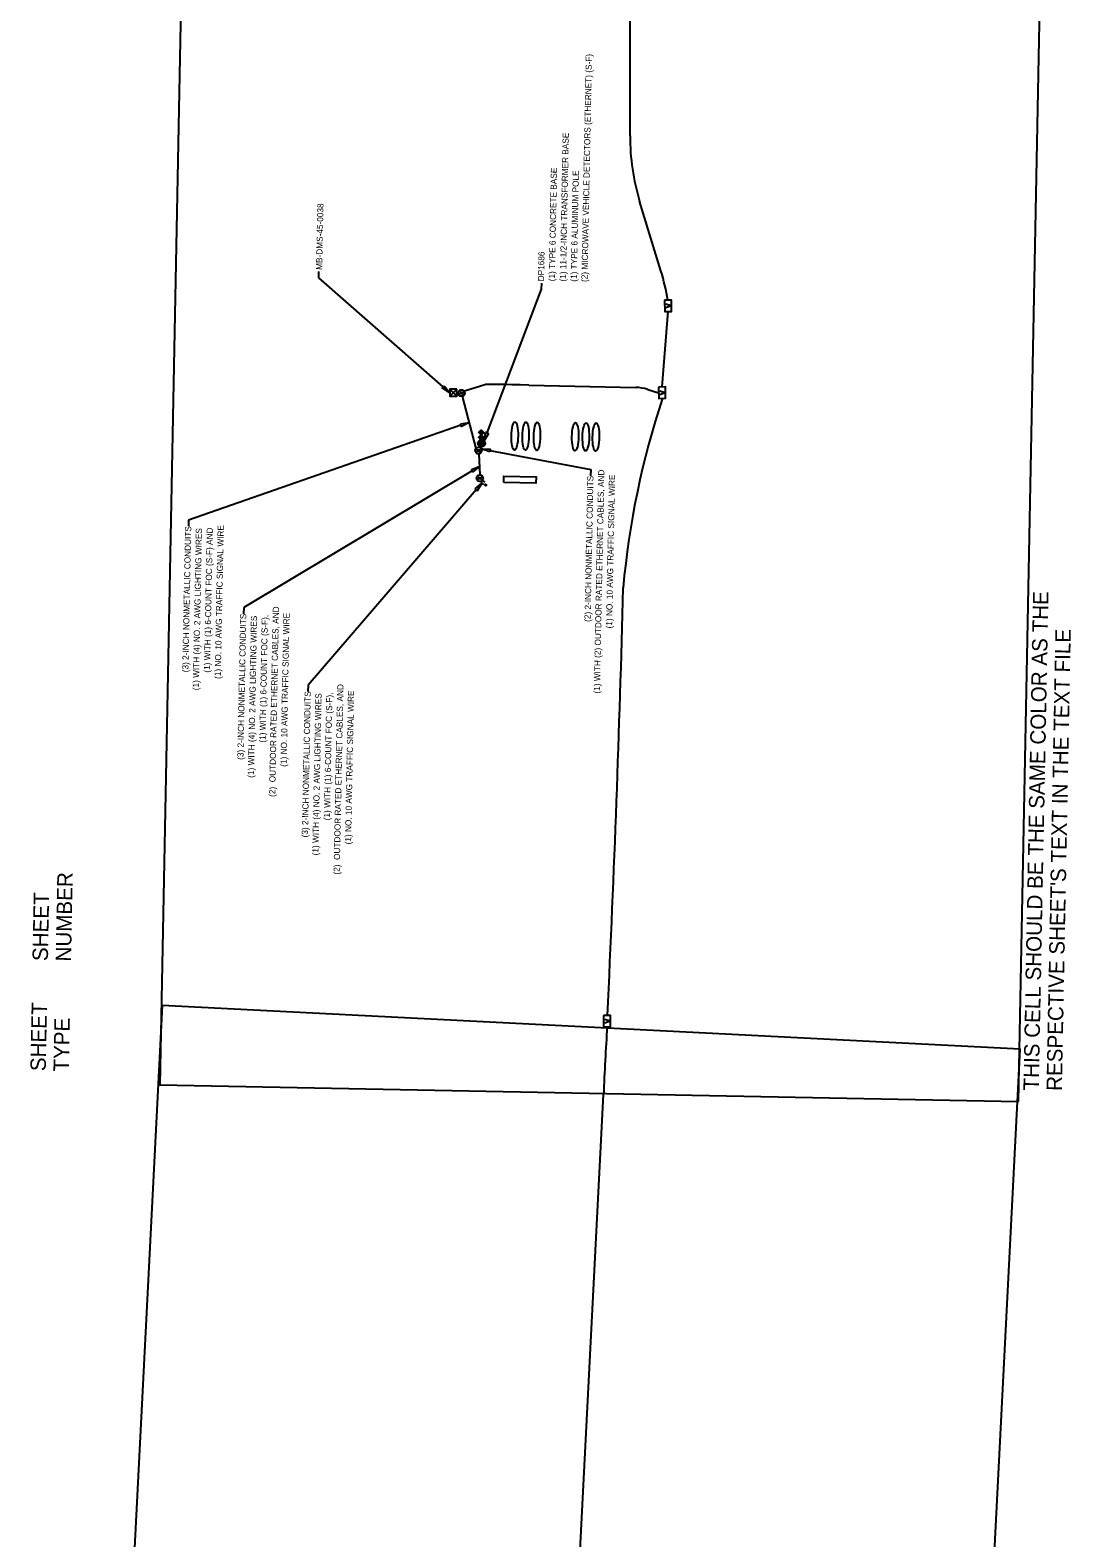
# Model space of a CAD drawing. Extents: x 601462 to 605493, y 331960 to 402715.
# Drawn here: x 602451 to 603632, y 391608 to 393320 of the extents above; entities that cross this region are included whole.
import ezdxf

# ---------------------------------------------------------------- set-up
doc = ezdxf.new("R2010")
doc.units = 0
for name, color, linetype in [('Default', 7, 'Continuous'), ('P_FTMS', 7, 'Continuous'), ('P_FTMSConduit', 7, 'Continuous'), ('P_MISC_TXT_1A (Construction)', 7, 'Continuous'), ('P_MISC_TXT_1B (Construction)', 7, 'Continuous')]:
    doc.layers.add(name, color=color, linetype=linetype)

# ---------------------------------------------------------------- blocks, each defined once
blk = doc.blocks.new('FMD')
at = {"layer": 'P_FTMS'}
for p, q in [((17, 18), (-17, 18)), ((-16, 16), (-16, 18)), ((16, 16), (-16, 16)), ((-15, 15), (-15, 20)), ((15, 19), (-15, 19)), ((15, 15), (-15, 15)), ((14, 20), (-14, 20)), ((13, 22), (-13, 22)), ((-13, 13), (-13, 21)), ((13, 13), (-13, 13)), ((-12, 12), (-12, 23)), ((12, 12), (-12, 12)), ((11, 23), (-11, 23)), ((10, 25), (-10, 25)), ((-10, 10), (-10, 24)), ((10, 10), (-10, 10)), ((-9, 9), (-9, 26)), ((9, 9), (-9, 9)), ((8, 26), (-8, 26)), ((7, 28), (-7, 28)), ((-7, 7), (-7, 27)), ((7, 7), (-7, 7)), ((-6, 6), (-6, 29)), ((6, 6), (-6, 6)), ((5, 29), (-5, 29)), ((4, 31), (-4, 31)), ((-4, 4), (-4, 30)), ((4, 4), (-4, 4)), ((-3, 3), (-3, 32)), ((3, 3), (-3, 3)), ((2, 32), (-2, 32)), ((1, 34), (-1, 34)), ((-1, 1), (-1, 33)), ((1, 1), (-1, 1)), ((0, 0), (0, 34)), ((1, 1), (1, 33)), ((3, 3), (3, 32)), ((4, 4), (4, 30)), ((6, 6), (6, 29)), ((7, 7), (7, 27)), ((9, 9), (9, 26)), ((10, 10), (10, 24)), ((12, 12), (12, 23)), ((13, 13), (13, 21)), ((15, 15), (15, 20)), ((16, 16), (16, 18))]:
    blk.add_line(p, q, dxfattribs=at)
blk.add_lwpolyline([(-17, 17), (0, 34), (17, 17), (0, 0)], close=True, dxfattribs=at)
blk = doc.blocks.new('FMB')
at = {"layer": 'P_FTMS'}
for p, q in [((24, -24), (-24, 24)), ((-24, -24), (24, 24))]:
    blk.add_line(p, q, dxfattribs=at)
blk.add_lwpolyline([(24, -24), (24, 24), (-24, 24), (-24, -24)], close=True, dxfattribs=at)
blk = doc.blocks.new('POINT_DISPLAY')
at = {"layer": 'Default'}
blk.add_line((0, 0), (0, 0), dxfattribs=at)
blk = doc.blocks.new('_U229')
at = {"layer": 'P_FTMS'}
for p, q in [((-4.5, 3.2), (1.5, -0.2)), ((-4.4, 2.8), (1.3, -0.4)), ((-4.3, 3.5), (1.8, 0)), ((-3.9, 3.4), (-4.3, 2.6)), ((-4.3, 2.4), (1, -0.6)), ((-3.5, 3.4), (-4.2, 2.2)), ((-4.2, 2), (0.7, -0.8)), ((-3.2, 3.3), (-4.1, 1.7)), ((-4.1, 1.6), (0.5, -1)), ((-2.9, 3.3), (-4, 1.3)), ((-4, 1.2), (0.2, -1.2)), ((-2.6, 3.2), (-3.9, 0.9)), ((-2.2, 3.2), (-3.8, 0.5)), ((-3.8, 0.7), (0, -1.4)), ((-1.9, 3.2), (-3.7, 0.1)), ((-3.7, 0.3), (-0.3, -1.6)), ((-3.5, 3.4), (2, 0.2)), ((-1.6, 3.1), (-3.5, -0.3)), ((-1.3, 3.1), (-3.4, -0.7)), ((-0.9, 3), (-3.3, -1.2)), ((-0.6, 3), (-3.2, -1.6)), ((-0.3, 2.9), (-3.1, -2)), ((0, 2.9), (-3, -2.4)), ((0.4, 2.8), (-2.9, -2.8)), ((-2.7, 3.3), (2.3, 0.4)), ((0.7, 2.8), (-2.7, -3.2)), ((1, 2.8), (-2.5, -3.4)), ((-1.9, 3.2), (2.5, 0.6)), ((1.3, 2.7), (-1.8, -2.9)), ((1.7, 2.7), (-1.2, -2.3)), ((-1.1, 3), (2.8, 0.8)), ((2, 2.6), (-0.5, -1.8)), ((-0.3, 2.9), (3.1, 1)), ((2.3, 2.6), (0.1, -1.3)), ((0.5, 2.8), (3.3, 1.2)), ((2.6, 2.5), (0.7, -0.8)), ((1.3, 2.7), (3.6, 1.4)), ((3, 2.5), (1.4, -0.3)), ((3.3, 2.4), (2, 0.2)), ((2.2, 2.6), (3.8, 1.6)), ((3.6, 2.4), (2.7, 0.7)), ((3, 2.5), (4.1, 1.8)), ((3.9, 2.3), (3.3, 1.2)), ((3.8, 2.4), (4.3, 2.1)), ((4.3, 2.3), (4, 1.7)), ((-3.6, -0.1), (-0.5, -1.8)), ((-3.5, -0.5), (-0.8, -2)), ((-3.4, -0.9), (-1.1, -2.2)), ((-3.3, -1.3), (-1.3, -2.4)), ((-3.2, -1.7), (-1.6, -2.7)), ((-3, -2.2), (-1.8, -2.9)), ((-2.9, -2.6), (-2.1, -3.1)), ((-2.8, -3), (-2.3, -3.3)), ((-2.7, -3.4), (-2.6, -3.5))]:
    blk.add_line(p, q, dxfattribs=at)
blk.add_lwpolyline([(-4.6, 3.5), (4.6, 2.3), (-2.7, -3.5)], close=True, dxfattribs=at)
blk.add_blockref('POINT_DISPLAY', (4.6, 2.3), dxfattribs=at)
blk = doc.blocks.new('_U231')
at = {"layer": 'P_FTMS'}
for p, q in [((12.1, 1.6), (-12.2, -0.1)), ((11.8, 3), (-12.1, 1.4)), ((11.9, 2.3), (-12.1, 0.6)), ((12.1, 0.8), (-12.1, -0.8)), ((12.1, 0.1), (-12.1, -1.6)), ((11.6, 3.7), (-12, 2.1)), ((-11.9, 2.5), (-11.4, -4.2)), ((11.3, 4.4), (-11.8, 2.9)), ((11, 5.2), (-11.6, 3.6)), ((10.6, 5.9), (-11.4, 4.4)), ((-11.3, 4.5), (-10.6, -6)), ((10.2, 6.6), (-11, 5.1)), ((9.8, 7.3), (-10.7, 5.9)), ((-10.7, 5.9), (-9.8, -7.2)), ((9.2, 8), (-10.2, 6.6)), ((-10, 6.9), (-9, -8.2)), ((8.6, 8.6), (-9.7, 7.4)), ((-9.3, 7.8), (-8.2, -9)), ((7.8, 9.3), (-9, 8.2)), ((-8.6, 8.5), (-7.4, -9.6)), ((6.9, 10), (-8.2, 9)), ((-8, 9.2), (-6.6, -10.2)), ((-7.3, 9.7), (-5.9, -10.6)), ((5.8, 10.7), (-7.2, 9.8)), ((-6.6, 10.3), (-5.1, -11)), ((4.5, 11.3), (-6, 10.6)), ((-5.9, 10.7), (-4.4, -11.4)), ((-5.1, 11), (-3.6, -11.6)), ((-4.4, 11.3), (-2.9, -11.8)), ((2.5, 11.9), (-4.1, 11.5)), ((-3.7, 11.6), (-2.1, -12)), ((-3, 11.8), (-1.4, -12.1)), ((-2.3, 12), (-0.6, -12.2)), ((-1.6, 12.1), (0.1, -12.2)), ((-0.8, 12.1), (0.8, -12.1)), ((-0.1, 12.2), (1.6, -12.1)), ((0.6, 12.1), (2.3, -11.9)), ((1.4, 12.1), (3, -11.8)), ((2.1, 12), (3.7, -11.6)), ((2.9, 11.8), (4.4, -11.3)), ((3.6, 11.6), (5.1, -11)), ((4.4, 11.3), (5.9, -10.7)), ((5.1, 11), (6.6, -10.2)), ((5.9, 10.6), (7.3, -9.8)), ((6.6, 10.2), (8, -9.2)), ((7.4, 9.7), (8.6, -8.6)), ((8.2, 9), (9.3, -7.8)), ((9, 8.2), (10, -6.9)), ((9.8, 7.2), (10.7, -5.8)), ((10.6, 5.9), (11.3, -4.5)), ((11.5, 4), (11.9, -2.5)), ((12.1, -0.6), (-12, -2.3)), ((12.1, -1.4), (-11.8, -3)), ((12, -2.1), (-11.6, -3.7)), ((11.8, -2.9), (-11.3, -4.4)), ((11.6, -3.6), (-11, -5.1)), ((11.3, -4.4), (-10.7, -5.9)), ((11.1, -5.1), (-10.2, -6.6)), ((10.6, -5.9), (-9.8, -7.3)), ((10.2, -6.6), (-9.2, -8)), ((9.6, -7.4), (-8.5, -8.6)), ((9, -8.2), (-7.8, -9.3)), ((8.2, -9), (-6.9, -10)), ((7.3, -9.8), (-5.8, -10.7)), ((6, -10.6), (-4.5, -11.3)), ((4.1, -11.5), (-2.6, -11.9))]:
    blk.add_line(p, q, dxfattribs=at)
blk.add_circle((0, 0), 12.2, dxfattribs=at)
blk = doc.blocks.new('FTMS_FCV')
at = {"layer": 'P_FTMS'}
blk.add_line((13, 16), (1, -22), dxfattribs=at)
blk.add_lwpolyline([(39, 24), (-39, 24), (-39, -24), (39, -24)], close=True, dxfattribs=at)
blk.add_lwpolyline([(-12, 16), (1, -22)], dxfattribs=at)

msp = doc.modelspace()

# ---------------------------------------------------------------- linework, layer by layer
at = {"layer": 'P_FTMS'}
for p, q in [((602988.2, 392806.4), (602988.4, 392813.5)), ((603024.7, 392805.7), (602988.2, 392806.4)), ((602988.4, 392813.5), (603024.9, 392812.8)), ((603024.9, 392812.8), (603024.7, 392805.7))]:
    msp.add_line(p, q, dxfattribs=at)
for points in [[(602778.4, 393038.9), (602778.5, 393045.9)], [(602919.5, 392915), (602778.4, 393038.9)], [(603031.1, 393025.9), (603031.3, 393032.9)], [(602969.4, 392862.8), (603031.1, 393025.9)], [(602939.6, 392871.4), (602630.5, 392763.8)], [(602972.6, 392842.8), (603087, 392821)], [(602952.4, 392819.8), (602693, 392664.4)], [(603087, 392821), (603086.9, 392814)], [(602957, 392798.1), (602766.2, 392576.3)], [(602630.5, 392763.8), (602630.3, 392756.8)], [(602693, 392664.4), (602692.8, 392657.4)], [(602766.2, 392576.3), (602766, 392569.3)]]:
    msp.add_lwpolyline(points, dxfattribs=at)
for points in [[(602920.6, 392916.3), (602927, 392908.4), (602918.4, 392913.8)], [(602939, 392873), (602949, 392874.7), (602940.1, 392869.9)], [(602970.9, 392862.2), (602965.8, 392853.4), (602967.8, 392863.4)], [(602972.3, 392841.1), (602962.8, 392844.6), (602972.9, 392844.4)], [(602951.6, 392821.3), (602961, 392825), (602953.3, 392818.4)], [(602988.2, 392806.4), (602988.4, 392813.5), (603024.9, 392812.8), (603024.7, 392805.7)], [(602955.7, 392799.2), (602963.5, 392805.7), (602958.2, 392797)]]:
    msp.add_lwpolyline(points, close=True, dxfattribs=at)
for centre in [(602940.3, 392908), (602959.6, 392842.6), (602961, 392811.3)]:
    msp.add_circle(centre, 3.75, dxfattribs=at)
for centre, start, end in [((602940.6, 392912.5), 212.6299, 318.8855), ((602940, 392903.5), 32.6299, 138.8855), ((602959.3, 392838.1), 32.6299, 138.8855), ((602959.9, 392847.1), 212.6299, 318.8855), ((602960.7, 392806.9), 32.6299, 138.8855), ((602961.4, 392815.8), 212.6299, 318.8855)]:
    msp.add_arc(centre, 3.75, start, end, dxfattribs=at)
for centre in [(603000.7, 392859.3), (603013.1, 392859.1), (603026, 392858.8), (603069.4, 392858.4), (603081.4, 392858.2), (603092.8, 392858)]:
    msp.add_ellipse(centre, major_axis=(0.3, 16), ratio=0.23471, dxfattribs=at)
at = {"layer": 'P_FTMSConduit'}
for p, q in [((603166.7, 393046.7), (603142.5, 393126)), ((603167.9, 392914.9), (603174.9, 393000.6)), ((602966.7, 392917.4), (602943.5, 392910)), ((603016.7, 392917), (603138.3, 392914.3)), ((603151.7, 392912.1), (603164, 392908.4)), ((602935, 392908.3), (602936.6, 392908.2)), ((602956.8, 392845.1), (602941.3, 392904.4)), ((602962.8, 392844.6), (602963, 392846.9)), ((602961.5, 392815.1), (602960.2, 392838.9)), ((602965.5, 392803.8), (602962.1, 392807.7)), ((602967.1, 392806.8), (602963.8, 392808.9))]:
    msp.add_line(p, q, dxfattribs=at)
msp.add_lwpolyline([(603029.4, 390707), (603101.5, 392111.6)], dxfattribs=at)
for centre, radius, start, end in [((580116.8, 393292.3), 23015.1, 359.77013, 0.20434), ((603381.6, 393198.9), 250, 179.7701, 196.9702), ((602927.6, 392973.7), 250, 9.1288, 16.9702), ((603137.2, 392864.3), 50, 73.0893, 88.7087), ((604075.5, 392601.9), 955.5, 161.6888, 174.8933), ((580116.8, 393292.3), 23015.1, 357.28329, 358.49277), ((610685.1, 391748.9), 7592.3, 176.6802, 177.2617)]:
    msp.add_arc(centre, radius, start, end, dxfattribs=at)
msp.add_ellipse((603016.6, 392916.3), major_axis=(-50, 1.1), ratio=0.014448, start_param=4.712389, end_param=6.247056, dxfattribs=at)
at = {"layer": 'P_MISC_TXT_1A (Construction)'}
msp.add_lwpolyline([(603494.1, 390590), (603574.4, 392162.9), (602600.6, 392212.6), (602520.3, 390639.7)], close=True, dxfattribs=at)
msp.add_lwpolyline([(603494.1, 390590), (603574.4, 392162.9), (602600.6, 392212.6), (602520.3, 390639.7)], close=True, dxfattribs=at)
at = {"layer": 'P_MISC_TXT_1B (Construction)'}
msp.add_lwpolyline([(603572.7, 392103.5), (603603.3, 393678.2), (602628.5, 393697.1), (602597.9, 392122.4)], close=True, dxfattribs=at)
msp.add_lwpolyline([(603572.7, 392103.5), (603603.3, 393678.2), (602628.5, 393697.1), (602597.9, 392122.4)], close=True, dxfattribs=at)

# ---------------------------------------------------------------- block references
at = {"layer": 'P_FTMS'}
for name, p, xscale, yscale, rotation in [('FTMS_FCV', (603174.8, 393007), 0.16404166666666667, 0.1640416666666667, 90.75145918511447), ('FMB', (602931, 392908.4), 0.16404166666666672, 0.16404166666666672, 89.4786762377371), ('FTMS_FCV', (603168, 392908.4), 0.16404166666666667, 0.1640416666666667, 90.75145918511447), ('FMD', (602959.8, 392857.8), 0.16404166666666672, 0.16404166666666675, -91.54665377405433), ('FMD', (602959.9, 392863.4), 0.16404166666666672, 0.16404166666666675, -91.54665377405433), ('_U231', (602963, 392850.9), 0.32808333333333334, 0.32808333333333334, 2.5604819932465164), ('_U229', (602967.8, 392803.7), 0.19685000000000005, 0.19685000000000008, 108.39132318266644), ('FTMS_FCV', (603105.5, 392195), 0.16404166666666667, 0.1640416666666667, 90.75145918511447)]:
    msp.add_blockref(name, p, dxfattribs=dict(at, xscale=xscale, yscale=yscale, rotation=rotation))

# ---------------------------------------------------------------- texts
for s, p in [('(2) MICROWAVE VEHICLE DETECTORS (ETHERNET) (S-F)', (603083.3, 393034)), ('(1) 11-1/2-INCH TRANSFORMER BASE', (603058.8, 393034.5)), ('(1) TYPE 6 CONCRETE BASE', (603046.2, 393034.8)), ('(1) TYPE 6 ALUMINUM POLE', (603071.1, 393034.3)), ('MB-DMS-45-0038', (602782.1, 393047.8)), ('DP1686', (603033.9, 393034.8)), ('(2) 2-INCH NONMETALLIC CONDUITS', (603086.8, 392648.1)), ('(1) WITH (2) OUTDOOR RATED ETHERNET CABLES, AND', (603097.4, 392566.7)), ('(1) NO. 10 AWG TRAFFIC SIGNAL WIRE', (603111.2, 392640.7)), ('(3) 2-INCH NONMETALLIC CONDUITS', (602630.2, 392590.9)), ('(1) WITH (1) 6-COUNT FOC (S-F) AND', (602654.8, 392590.4)), ('(1) NO. 10 AWG TRAFFIC SIGNAL WIRE', (602667, 392583.3)), ('(1) WITH (4) NO. 2 AWG LIGHTING WIRES', (602642.1, 392570.5)), ('(3) 2-INCH NONMETALLIC CONDUITS', (602692.7, 392491.5)), ('(1) WITH (4) NO. 2 AWG LIGHTING WIRES', (602704.6, 392471.1)), ('(1) WITH (1) 6-COUNT FOC (S-F),', (602717.7, 392511)), ('OUTDOOR RATED ETHERNET CABLES, AND', (602729.1, 392466)), ('(1) NO. 10 AWG TRAFFIC SIGNAL WIRE', (602741.7, 392483.6)), ('(3) 2-INCH NONMETALLIC CONDUITS', (602765.9, 392403.4)), ('(1) WITH (4) NO. 2 AWG LIGHTING WIRES', (602777.8, 392383)), ('(1) WITH (1) 6-COUNT FOC (S-F),', (602790.9, 392422.8)), ('OUTDOOR RATED ETHERNET CABLES, AND', (602802.3, 392377.8)), ('(1) NO. 10 AWG TRAFFIC SIGNAL WIRE', (602814.9, 392395.5)), ('(2)', (602728.8, 392449.4)), ('(2)', (602802, 392361.2))]:
    msp.add_text(s, height=7, rotation=88.8592, dxfattribs=at).set_placement(p)
at = {"layer": 'P_MISC_TXT_1B (Construction)'}
for s, p in [('THIS CELL SHOULD BE THE SAME COLOR AS THE', (603595.6, 392116)), ('THIS CELL SHOULD BE THE SAME COLOR AS THE', (603595.6, 392116)), ("RESPECTIVE SHEET'S TEXT IN THE TEXT FILE", (603621.8, 392115.5)), ("RESPECTIVE SHEET'S TEXT IN THE TEXT FILE", (603621.8, 392115.5)), ('NUMBER', (602497, 392262.4)), ('NUMBER', (602497, 392262.4)), ('SHEET', (602470.7, 392262.9)), ('SHEET', (602470.7, 392262.9)), ('SHEET', (602468.3, 392137.9)), ('SHEET', (602468.3, 392137.9)), ('TYPE', (602494.5, 392137.4)), ('TYPE', (602494.5, 392137.4))]:
    msp.add_text(s, height=17.5, rotation=88.8847, dxfattribs=at).set_placement(p)

doc.saveas('drawing.dxf')
